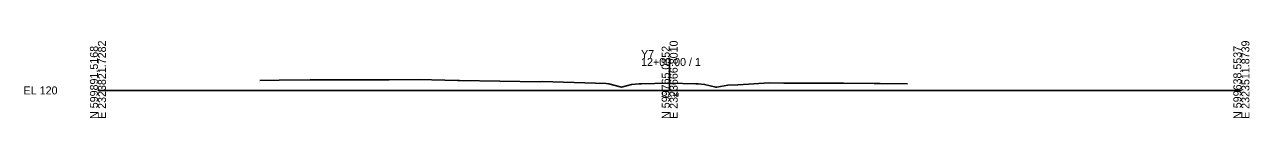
# Model space of a CAD drawing. Extents: x -26 to 3203, y -10 to 1017.
# Drawn here: x -25.7 to 402.8, y -9.7 to 17.3 of the extents above; entities that cross this region are included whole.
import ezdxf

# ---------------------------------------------------------------- set-up
doc = ezdxf.new("R2010")
doc.units = 0
for name, color, linetype in [('Default', 7, 'Continuous'), ('Exist Cross Section Cell', 7, 'Continuous'), ('Exist XS Center Line Elevation Label', 7, 'Continuous'), ('Exist XS Ground Line', 7, 'Continuous')]:
    doc.layers.add(name, color=color, linetype=linetype)

msp = doc.modelspace()

# ---------------------------------------------------------------- linework, layer by layer
at = {"layer": 'Exist Cross Section Cell'}
for p, q in [((200, 0), (200, 11.36)), ((0, 0), (200, 0)), ((200, 0), (400, 0))]:
    msp.add_line(p, q, dxfattribs=at)
at = {"layer": 'Exist XS Ground Line'}
msp.add_lwpolyline([(56.66, 3.43), (63.43, 3.58), (74.27, 3.67), (79.51, 3.71), (92.55, 3.68), (97.37, 3.66), (98.96, 3.66), (99.76, 3.66), (100.21, 3.65), (100.57, 3.65), (101.87, 3.66), (112.11, 3.79), (121.38, 3.55), (125.82, 3.46), (126.49, 3.45), (140.59, 3.26), (154.67, 3.06), (155.36, 3.08), (177.8, 2.39), (178.71, 2.32), (183.15, 1.18), (186.65, 2.02), (189.38, 2.34), (190.15, 2.35), (199.24, 2.5), (200, 2.49), (209.12, 2.36), (209.93, 2.35), (212.2, 2.12), (216.12, 1.13), (216.45, 1.18), (220.39, 1.87), (223.87, 2.01), (234.95, 2.63), (239.92, 2.56), (244.29, 2.58), (247.86, 2.48), (255.74, 2.49), (258.51, 2.53), (260.77, 2.55), (271.55, 2.47), (272.73, 2.44), (273.68, 2.44), (283.16, 2.33)], dxfattribs=at)
msp.add_lwpolyline([(56.66, 3.43), (63.43, 3.58), (74.27, 3.67), (79.51, 3.71), (92.55, 3.68), (97.37, 3.66), (98.96, 3.66), (99.76, 3.66), (100.21, 3.65), (100.57, 3.65), (101.87, 3.66), (112.11, 3.79), (121.38, 3.55), (125.82, 3.46), (126.49, 3.45), (140.59, 3.26), (154.67, 3.06), (155.36, 3.08), (177.8, 2.39), (178.71, 2.32), (183.15, 1.18), (186.65, 2.02), (189.38, 2.34), (190.15, 2.35), (199.24, 2.5), (200, 2.49), (209.12, 2.36), (209.93, 2.35), (212.2, 2.12), (216.12, 1.13), (216.45, 1.18), (220.39, 1.87), (223.87, 2.01), (234.95, 2.63), (239.92, 2.56), (244.29, 2.58), (247.86, 2.48), (255.74, 2.49), (258.51, 2.53), (260.77, 2.55), (271.55, 2.47), (272.73, 2.44), (273.68, 2.44), (283.16, 2.33)], dxfattribs=at)

# ---------------------------------------------------------------- texts
at = {"layer": 'Default'}
msp.add_text('-', height=0.0001, dxfattribs=at).set_placement((0, 0))
at = {"layer": 'Exist Cross Section Cell'}
for s, p in [('E 2323821.7282', (2.8, -10)), ('E 2323666.8010', (202.8, -10)), ('E 2323511.8739', (402.8, -10)), ('N 599891.5168', (0, -10)), ('N 599765.0352', (200, -10)), ('N 599638.5537', (400, -10))]:
    msp.add_text(s, height=2.8, rotation=90, dxfattribs=at).set_placement(p)
for s, p in [('Y7', (190, 11.36)), ('12+00.00 / 1', (190, 8.56)), ('EL 120', (-26, -1.4))]:
    msp.add_text(s, height=2.8, dxfattribs=at).set_placement(p)
at = {"layer": 'Exist XS Center Line Elevation Label'}
msp.add_text('122.49', height=1.5, dxfattribs=at).set_placement((196.94, -2.26))
msp.add_text('122.49', height=1.5, dxfattribs=at).set_placement((196.94, -2.26))

doc.saveas('drawing.dxf')
